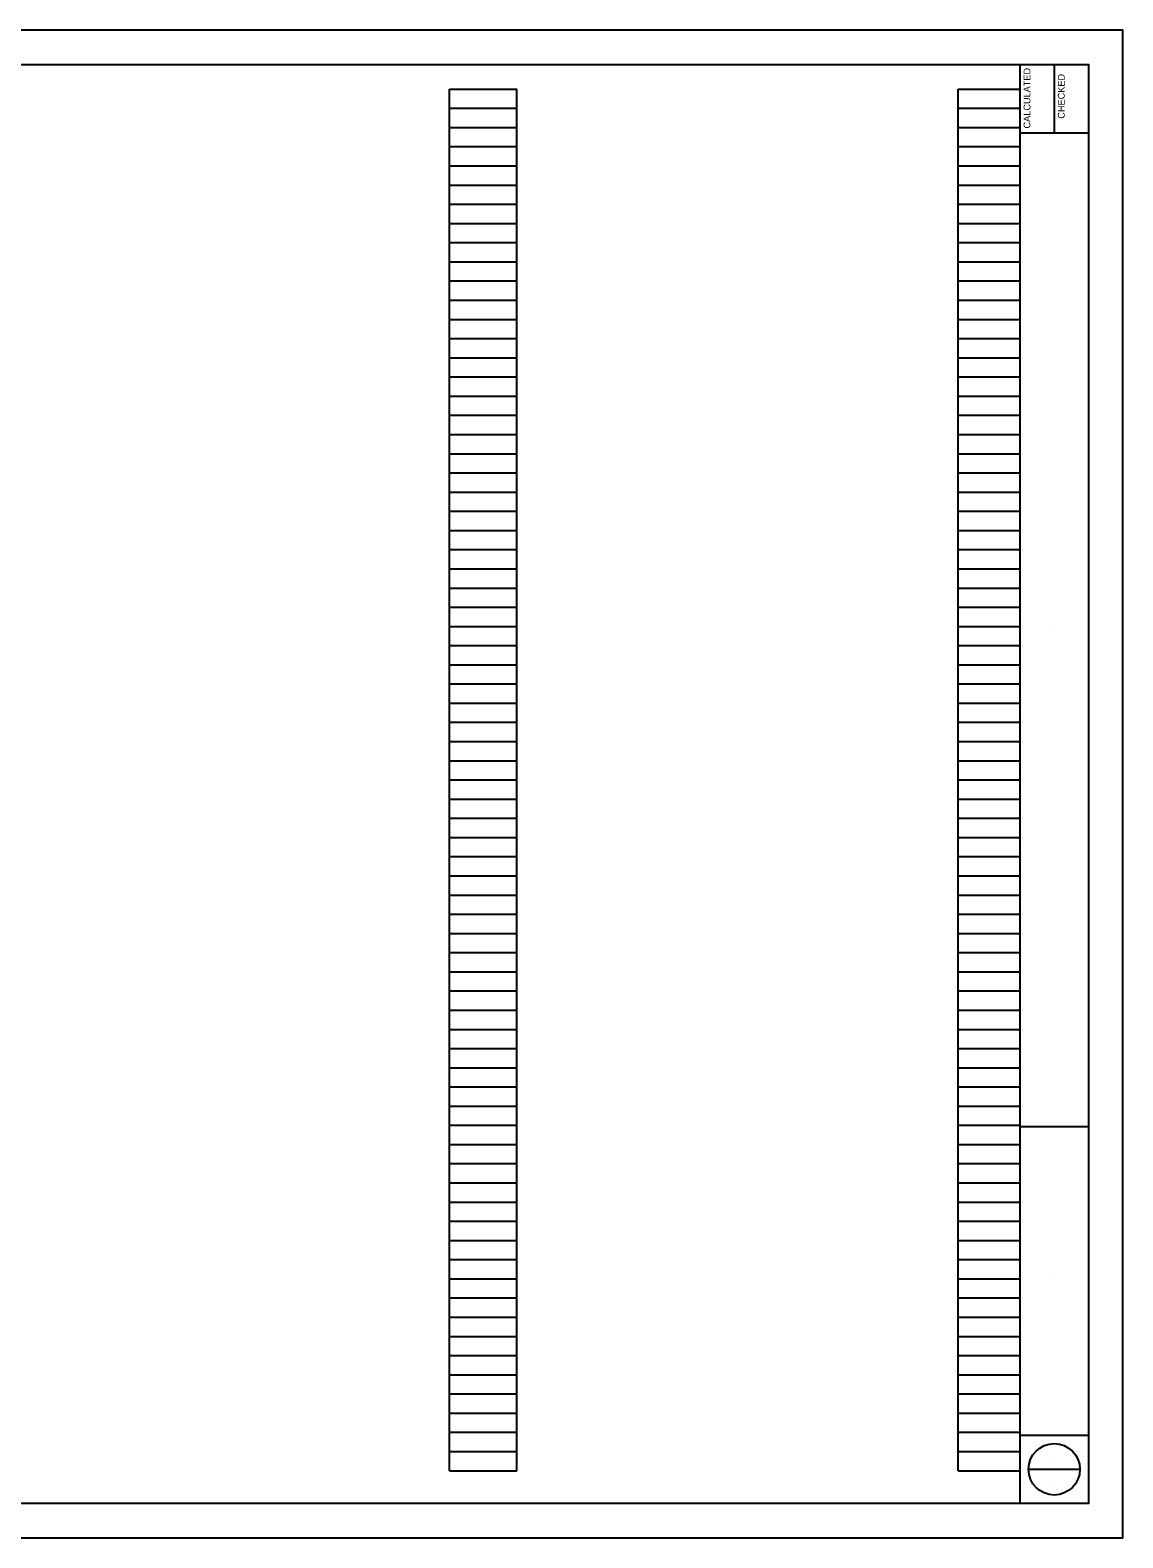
# Model space of a CAD drawing. Extents: x -31.1 to 65.6, y 0 to 22.
# Drawn here: x 18.06 to 34, y 0 to 22 of the extents above; entities that cross this region are included whole.
import ezdxf

# ---------------------------------------------------------------- set-up
doc = ezdxf.new("R2010")
doc.units = 0
for name, color, linetype in [('SH_Border', 7, 'Continuous'), ('SH_Cut_Line', 7, 'Continuous'), ('SH_Data', 7, 'Continuous')]:
    doc.layers.add(name, color=color, linetype=linetype)

msp = doc.modelspace()

# ---------------------------------------------------------------- linework, layer by layer
at = {"layer": 'SH_Border'}
for p, q in [((32.5, 0.5), (32.5, 21.5)), ((33, 21.5), (33, 20.5)), ((32.5, 20.5), (33.5, 20.5)), ((32.5, 6), (33.5, 6)), ((32.5, 1.5), (33.5, 1.5))]:
    msp.add_line(p, q, dxfattribs=at)
msp.add_lwpolyline([(2, 21.5), (33.5, 21.5), (33.5, 0.5), (2, 0.5)], close=True, dxfattribs=at)
at = {"layer": 'SH_Cut_Line'}
msp.add_lwpolyline([(0, 0), (34, 0), (34, 22), (0, 22)], close=True, dxfattribs=at)
at = {"layer": 'SH_Data'}
for p, q in [((24.18, 0.98), (24.18, 21.14)), ((24.18, 21.14), (25.16, 21.14)), ((25.16, 0.98), (25.16, 21.14)), ((31.6, 0.98), (31.6, 21.14)), ((31.6, 21.14), (32.5, 21.14)), ((32.5, 0.98), (32.5, 21.14)), ((32.92, 21.004), (32.92, 21.004)), ((33.42, 21.004), (33.42, 21.004)), ((24.18, 20.86), (25.16, 20.86)), ((31.6, 20.86), (32.5, 20.86)), ((24.18, 20.58), (25.16, 20.58)), ((31.6, 20.58), (32.5, 20.58)), ((24.18, 20.3), (25.16, 20.3)), ((31.6, 20.3), (32.5, 20.3)), ((24.18, 20.02), (25.16, 20.02)), ((31.6, 20.02), (32.5, 20.02)), ((24.18, 19.74), (25.16, 19.74)), ((31.6, 19.74), (32.5, 19.74)), ((24.18, 19.46), (25.16, 19.46)), ((31.6, 19.46), (32.5, 19.46)), ((24.18, 19.18), (25.16, 19.18)), ((31.6, 19.18), (32.5, 19.18)), ((24.18, 18.9), (25.16, 18.9)), ((31.6, 18.9), (32.5, 18.9)), ((24.18, 18.62), (25.16, 18.62)), ((31.6, 18.62), (32.5, 18.62)), ((24.18, 18.34), (25.16, 18.34)), ((31.6, 18.34), (32.5, 18.34)), ((24.18, 18.06), (25.16, 18.06)), ((31.6, 18.06), (32.5, 18.06)), ((24.18, 17.78), (25.16, 17.78)), ((31.6, 17.78), (32.5, 17.78)), ((24.18, 17.5), (25.16, 17.5)), ((31.6, 17.5), (32.5, 17.5)), ((24.18, 17.22), (25.16, 17.22)), ((31.6, 17.22), (32.5, 17.22)), ((24.18, 16.94), (25.16, 16.94)), ((31.6, 16.94), (32.5, 16.94)), ((24.18, 16.66), (25.16, 16.66)), ((31.6, 16.66), (32.5, 16.66)), ((24.18, 16.38), (25.16, 16.38)), ((31.6, 16.38), (32.5, 16.38)), ((24.18, 16.1), (25.16, 16.1)), ((31.6, 16.1), (32.5, 16.1)), ((24.18, 15.82), (25.16, 15.82)), ((31.6, 15.82), (32.5, 15.82)), ((24.18, 15.54), (25.16, 15.54)), ((31.6, 15.54), (32.5, 15.54)), ((24.18, 15.26), (25.16, 15.26)), ((31.6, 15.26), (32.5, 15.26)), ((24.18, 14.98), (25.16, 14.98)), ((31.6, 14.98), (32.5, 14.98)), ((24.18, 14.7), (25.16, 14.7)), ((31.6, 14.7), (32.5, 14.7)), ((24.18, 14.42), (25.16, 14.42)), ((31.6, 14.42), (32.5, 14.42)), ((24.18, 14.14), (25.16, 14.14)), ((31.6, 14.14), (32.5, 14.14)), ((24.18, 13.86), (25.16, 13.86)), ((31.6, 13.86), (32.5, 13.86)), ((24.18, 13.58), (25.16, 13.58)), ((31.6, 13.58), (32.5, 13.58)), ((24.18, 13.3), (25.16, 13.3)), ((31.6, 13.3), (32.5, 13.3)), ((33, 13.292), (33, 13.292)), ((24.18, 13.02), (25.16, 13.02)), ((31.6, 13.02), (32.5, 13.02)), ((24.18, 12.74), (25.16, 12.74)), ((31.6, 12.74), (32.5, 12.74)), ((24.18, 12.46), (25.16, 12.46)), ((31.6, 12.46), (32.5, 12.46)), ((24.18, 12.18), (25.16, 12.18)), ((31.6, 12.18), (32.5, 12.18)), ((24.18, 11.9), (25.16, 11.9)), ((31.6, 11.9), (32.5, 11.9)), ((24.18, 11.62), (25.16, 11.62)), ((31.6, 11.62), (32.5, 11.62)), ((24.18, 11.34), (25.16, 11.34)), ((31.6, 11.34), (32.5, 11.34)), ((24.18, 11.06), (25.16, 11.06)), ((31.6, 11.06), (32.5, 11.06)), ((24.18, 10.78), (25.16, 10.78)), ((31.6, 10.78), (32.5, 10.78)), ((24.18, 10.5), (25.16, 10.5)), ((31.6, 10.5), (32.5, 10.5)), ((24.18, 10.22), (25.16, 10.22)), ((31.6, 10.22), (32.5, 10.22)), ((24.18, 9.94), (25.16, 9.94)), ((31.6, 9.94), (32.5, 9.94)), ((24.18, 9.66), (25.16, 9.66)), ((31.6, 9.66), (32.5, 9.66)), ((24.18, 9.38), (25.16, 9.38)), ((31.6, 9.38), (32.5, 9.38)), ((24.18, 9.1), (25.16, 9.1)), ((31.6, 9.1), (32.5, 9.1)), ((24.18, 8.82), (25.16, 8.82)), ((31.6, 8.82), (32.5, 8.82)), ((24.18, 8.54), (25.16, 8.54)), ((31.6, 8.54), (32.5, 8.54)), ((24.18, 8.26), (25.16, 8.26)), ((31.6, 8.26), (32.5, 8.26)), ((24.18, 7.98), (25.16, 7.98)), ((31.6, 7.98), (32.5, 7.98)), ((24.18, 7.7), (25.16, 7.7)), ((31.6, 7.7), (32.5, 7.7)), ((24.18, 7.42), (25.16, 7.42)), ((31.6, 7.42), (32.5, 7.42)), ((24.18, 7.14), (25.16, 7.14)), ((31.6, 7.14), (32.5, 7.14)), ((24.18, 6.86), (25.16, 6.86)), ((31.6, 6.86), (32.5, 6.86)), ((24.18, 6.58), (25.16, 6.58)), ((31.6, 6.58), (32.5, 6.58)), ((24.18, 6.3), (25.16, 6.3)), ((31.6, 6.3), (32.5, 6.3)), ((24.18, 6.02), (25.16, 6.02)), ((31.6, 6.02), (32.5, 6.02)), ((24.18, 5.74), (25.16, 5.74)), ((31.6, 5.74), (32.5, 5.74)), ((24.18, 5.46), (25.16, 5.46)), ((31.6, 5.46), (32.5, 5.46)), ((24.18, 5.18), (25.16, 5.18)), ((31.6, 5.18), (32.5, 5.18)), ((24.18, 4.9), (25.16, 4.9)), ((31.6, 4.9), (32.5, 4.9)), ((24.18, 4.62), (25.16, 4.62)), ((31.6, 4.62), (32.5, 4.62)), ((24.18, 4.34), (25.16, 4.34)), ((31.6, 4.34), (32.5, 4.34)), ((24.18, 4.06), (25.16, 4.06)), ((31.6, 4.06), (32.5, 4.06)), ((24.18, 3.78), (25.16, 3.78)), ((31.6, 3.78), (32.5, 3.78)), ((33, 3.792), (33, 3.792)), ((24.18, 3.5), (25.16, 3.5)), ((31.6, 3.5), (32.5, 3.5)), ((24.18, 3.22), (25.16, 3.22)), ((31.6, 3.22), (32.5, 3.22)), ((24.18, 2.94), (25.16, 2.94)), ((31.6, 2.94), (32.5, 2.94)), ((24.18, 2.66), (25.16, 2.66)), ((31.6, 2.66), (32.5, 2.66)), ((24.18, 2.38), (25.16, 2.38)), ((31.6, 2.38), (32.5, 2.38)), ((24.18, 2.1), (25.16, 2.1)), ((31.6, 2.1), (32.5, 2.1)), ((24.18, 1.82), (25.16, 1.82)), ((31.6, 1.82), (32.5, 1.82)), ((24.18, 1.54), (25.16, 1.54)), ((31.6, 1.54), (32.5, 1.54)), ((24.18, 1.26), (25.16, 1.26)), ((31.6, 1.26), (32.5, 1.26)), ((24.18, 0.98), (25.16, 0.98)), ((31.6, 0.98), (32.5, 0.98)), ((32.625, 1), (33.375, 1)), ((33, 1.085), (33, 1.085)), ((33, 0.745), (33, 0.745))]:
    msp.add_line(p, q, dxfattribs=at)
msp.add_circle((33, 1), 0.375, dxfattribs=at)

# ---------------------------------------------------------------- texts
for s, p in [('CALCULATED', (32.652, 20.565)), ('CHECKED', (33.152, 20.708))]:
    msp.add_text(s, height=0.1, rotation=90, dxfattribs=at).set_placement(p)

doc.saveas('drawing.dxf')
